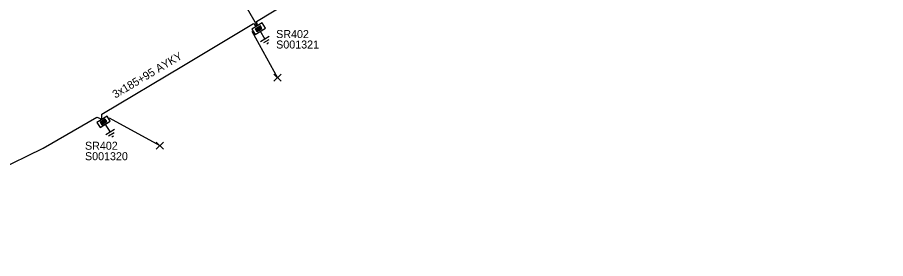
# Model space of a CAD drawing. Extents: x -762500 to -761285, y -1155006 to -1154135.
# Drawn here: x -761909.8 to -761802, y -1154887.3 to -1154857.3 of the extents above; entities that cross this region are included whole.
import ezdxf

# ---------------------------------------------------------------- set-up
doc = ezdxf.new("R2010")
doc.units = 0
for name, color, linetype in [('Vrstva 15', 7, 'Continuous'), ('Vrstva 28', 7, 'Continuous'), ('Vrstva 29', 7, 'Continuous'), ('Vrstva 30', 7, 'Continuous'), ('Vrstva 34', 7, 'Continuous'), ('Vrstva 5', 7, 'Continuous'), ('Vrstva 59', 7, 'Continuous'), ('Vrstva 6', 7, 'Continuous')]:
    doc.layers.add(name, color=color, linetype=linetype)

msp = doc.modelspace()

# ---------------------------------------------------------------- linework, layer by layer
at = {"layer": 'Vrstva 15'}
for points in [[(-761879.686, -1154858.967), (-761879.043, -1154860.038)], [(-761878.507, -1154859.716), (-761879.578, -1154860.36)], [(-761878.554, -1154860.106), (-761879.229, -1154860.512)], [(-761878.721, -1154860.574), (-761878.83, -1154860.64)], [(-761878.607, -1154860.506), (-761878.721, -1154860.574)], [(-761898.937, -1154870.531), (-761898.275, -1154871.591)], [(-761897.745, -1154871.26), (-761898.805, -1154871.922)], [(-761897.785, -1154871.65), (-761898.453, -1154872.068)], [(-761897.944, -1154872.121), (-761898.052, -1154872.189)], [(-761897.831, -1154872.05), (-761897.944, -1154872.121)]]:
    msp.add_lwpolyline(points, dxfattribs=at)
at = {"layer": 'Vrstva 28'}
for points in [[(-761879.377, -1154858.03), (-761880.663, -1154858.802)], [(-761879.612, -1154858.384), (-761880.25, -1154858.767)], [(-761879.628, -1154858.449), (-761880.185, -1154858.784)], [(-761879.644, -1154858.514), (-761880.12, -1154858.8)], [(-761879.661, -1154858.579), (-761880.055, -1154858.816)], [(-761879.996, -1154858.835), (-761879.672, -1154858.64)], [(-761879.612, -1154858.66), (-761879.661, -1154858.579)], [(-761879.547, -1154858.676), (-761879.644, -1154858.514)], [(-761879.482, -1154858.692), (-761879.628, -1154858.449)], [(-761879.417, -1154858.708), (-761879.612, -1154858.384)], [(-761878.991, -1154858.672), (-761879.377, -1154858.03)], [(-761880.663, -1154858.802), (-761880.277, -1154859.445)], [(-761880.277, -1154859.445), (-761878.991, -1154858.672)], [(-761880.25, -1154858.767), (-761880.055, -1154859.091)], [(-761880.185, -1154858.784), (-761880.039, -1154859.027)], [(-761880.12, -1154858.8), (-761880.023, -1154858.962)], [(-761880.055, -1154859.091), (-761879.417, -1154858.708)], [(-761880.055, -1154858.816), (-761880.007, -1154858.897)], [(-761880.039, -1154859.027), (-761879.482, -1154858.692)], [(-761880.023, -1154858.962), (-761879.547, -1154858.676)], [(-761880.007, -1154858.897), (-761879.612, -1154858.66)], [(-761898.644, -1154869.588), (-761899.916, -1154870.383)], [(-761899.916, -1154870.383), (-761899.519, -1154871.019)], [(-761899.519, -1154871.019), (-761898.247, -1154870.224)], [(-761898.872, -1154869.947), (-761899.503, -1154870.341)], [(-761899.503, -1154870.341), (-761899.303, -1154870.662)], [(-761898.887, -1154870.012), (-761899.438, -1154870.356)], [(-761899.438, -1154870.356), (-761899.288, -1154870.597)], [(-761898.902, -1154870.077), (-761899.373, -1154870.371)], [(-761899.373, -1154870.371), (-761899.273, -1154870.532)], [(-761898.917, -1154870.142), (-761899.308, -1154870.387)], [(-761899.308, -1154870.387), (-761899.258, -1154870.467)], [(-761899.303, -1154870.662), (-761898.672, -1154870.268)], [(-761899.288, -1154870.597), (-761898.737, -1154870.253)], [(-761899.273, -1154870.532), (-761898.802, -1154870.238)], [(-761899.258, -1154870.467), (-761898.867, -1154870.223)], [(-761899.248, -1154870.405), (-761898.928, -1154870.204)], [(-761898.867, -1154870.223), (-761898.917, -1154870.142)], [(-761898.802, -1154870.238), (-761898.902, -1154870.077)], [(-761898.737, -1154870.253), (-761898.887, -1154870.012)], [(-761898.672, -1154870.268), (-761898.872, -1154869.947)], [(-761898.247, -1154870.224), (-761898.644, -1154869.588)]]:
    msp.add_lwpolyline(points, dxfattribs=at)
at = {"layer": 'Vrstva 34'}
for points in [[(-761877.922, -1154864.378), (-761877.038, -1154865.262)], [(-761877.922, -1154865.262), (-761877.038, -1154864.378)], [(-761892.532, -1154872.808), (-761891.648, -1154873.692)], [(-761892.532, -1154873.692), (-761891.648, -1154872.808)]]:
    msp.add_lwpolyline(points, dxfattribs=at)
at = {"layer": 'Vrstva 5'}
for points in [[(-761879.97, -1154858.24), (-761880.08, -1154857.83), (-761869.96, -1154851.69), (-761872.58, -1154847.37), (-761866.96, -1154843.98), (-761869.19, -1154839.6), (-761811.93, -1154804.88), (-761805.65, -1154813.7), (-761802.76, -1154811.9), (-761801.97, -1154812.04)], [(-762005.61, -1154816.29), (-762007.05, -1154819.38), (-762002.97, -1154821.02), (-762002.81, -1154821.33), (-761985.36, -1154828.06), (-761983.62, -1154828.19), (-761980.61, -1154827.74), (-761973.18, -1154830.37), (-761944.98, -1154847.33), (-761938.84, -1154848.76), (-761929.52, -1154843.04), (-761920.87, -1154857.05), (-761881.47, -1154834.36), (-761875.67, -1154843.65), (-761885.32, -1154849.18), (-761880.3, -1154857.9), (-761880.08, -1154858.31)], [(-761899.29, -1154869.84), (-761899.29, -1154869.35), (-761889.14, -1154863.3), (-761880.46, -1154858.1), (-761880.2, -1154858.37)], [(-761956.56, -1154882.84), (-761956.17, -1154882.41), (-761954.07, -1154883.16), (-761939.35, -1154887.07), (-761935.63, -1154887.27), (-761918.14, -1154879.2), (-761906.58, -1154873.55), (-761899.9, -1154869.73), (-761899.4, -1154869.91)]]:
    msp.add_lwpolyline(points, dxfattribs=at)
at = {"layer": 'Vrstva 59'}
for points in [[(-761880.66, -1154859.05), (-761877.48, -1154864.82)], [(-761898.37, -1154869.78), (-761892.09, -1154873.25)]]:
    msp.add_lwpolyline(points, dxfattribs=at)

# ---------------------------------------------------------------- texts
at = {"layer": 'Vrstva 29'}
for s, p in [('S001321', (-761877.65, -1154861.2)), ('S001320', (-761901.39, -1154875.06))]:
    msp.add_text(s, height=0.9943, dxfattribs=at).set_placement(p)
at = {"layer": 'Vrstva 30'}
for p in [(-761877.65, -1154859.9), (-761901.39, -1154873.76)]:
    msp.add_text('SR402', height=0.9943, dxfattribs=at).set_placement(p)
at = {"layer": 'Vrstva 6'}
msp.add_text('3x185+95 AYKY', height=0.99429, rotation=30.79993, dxfattribs=at).set_placement((-761897.62, -1154867.42))

doc.saveas('drawing.dxf')
